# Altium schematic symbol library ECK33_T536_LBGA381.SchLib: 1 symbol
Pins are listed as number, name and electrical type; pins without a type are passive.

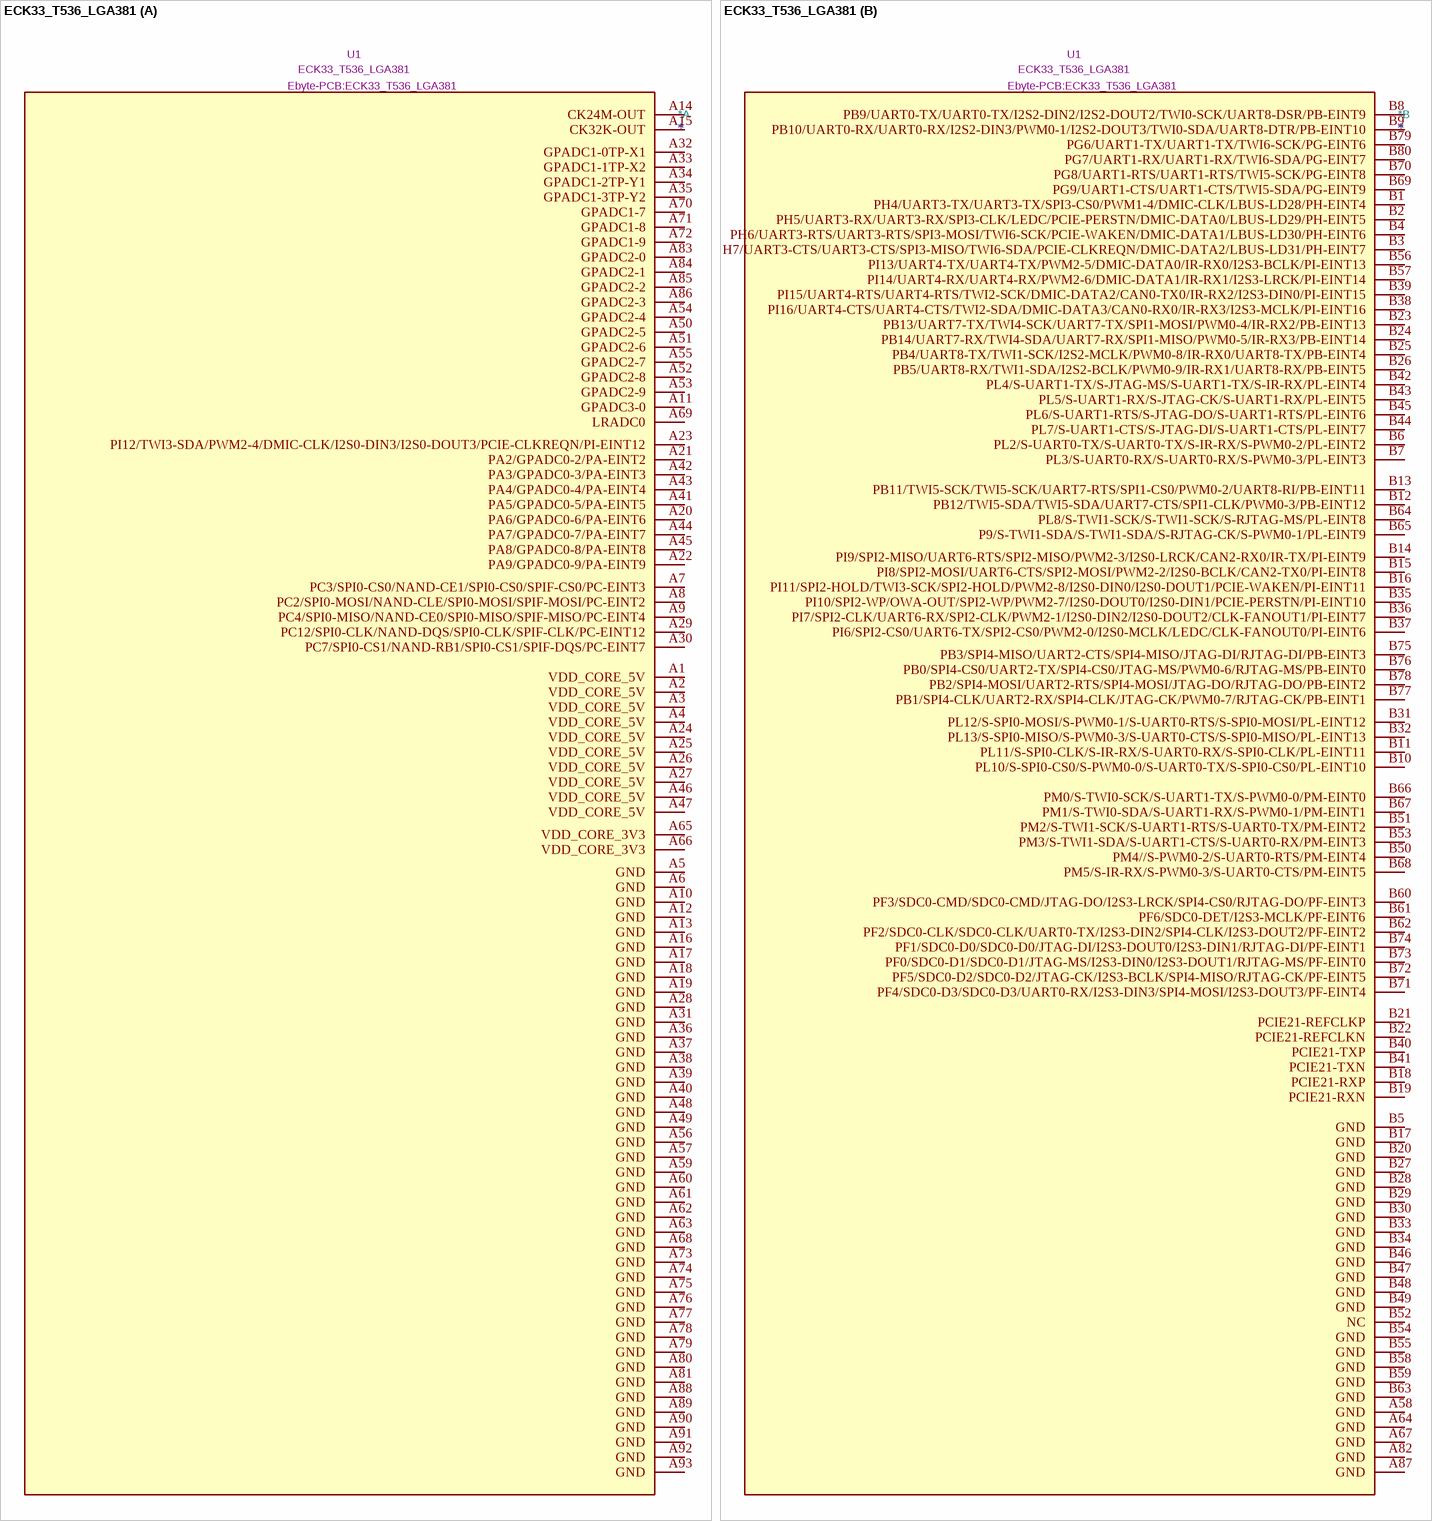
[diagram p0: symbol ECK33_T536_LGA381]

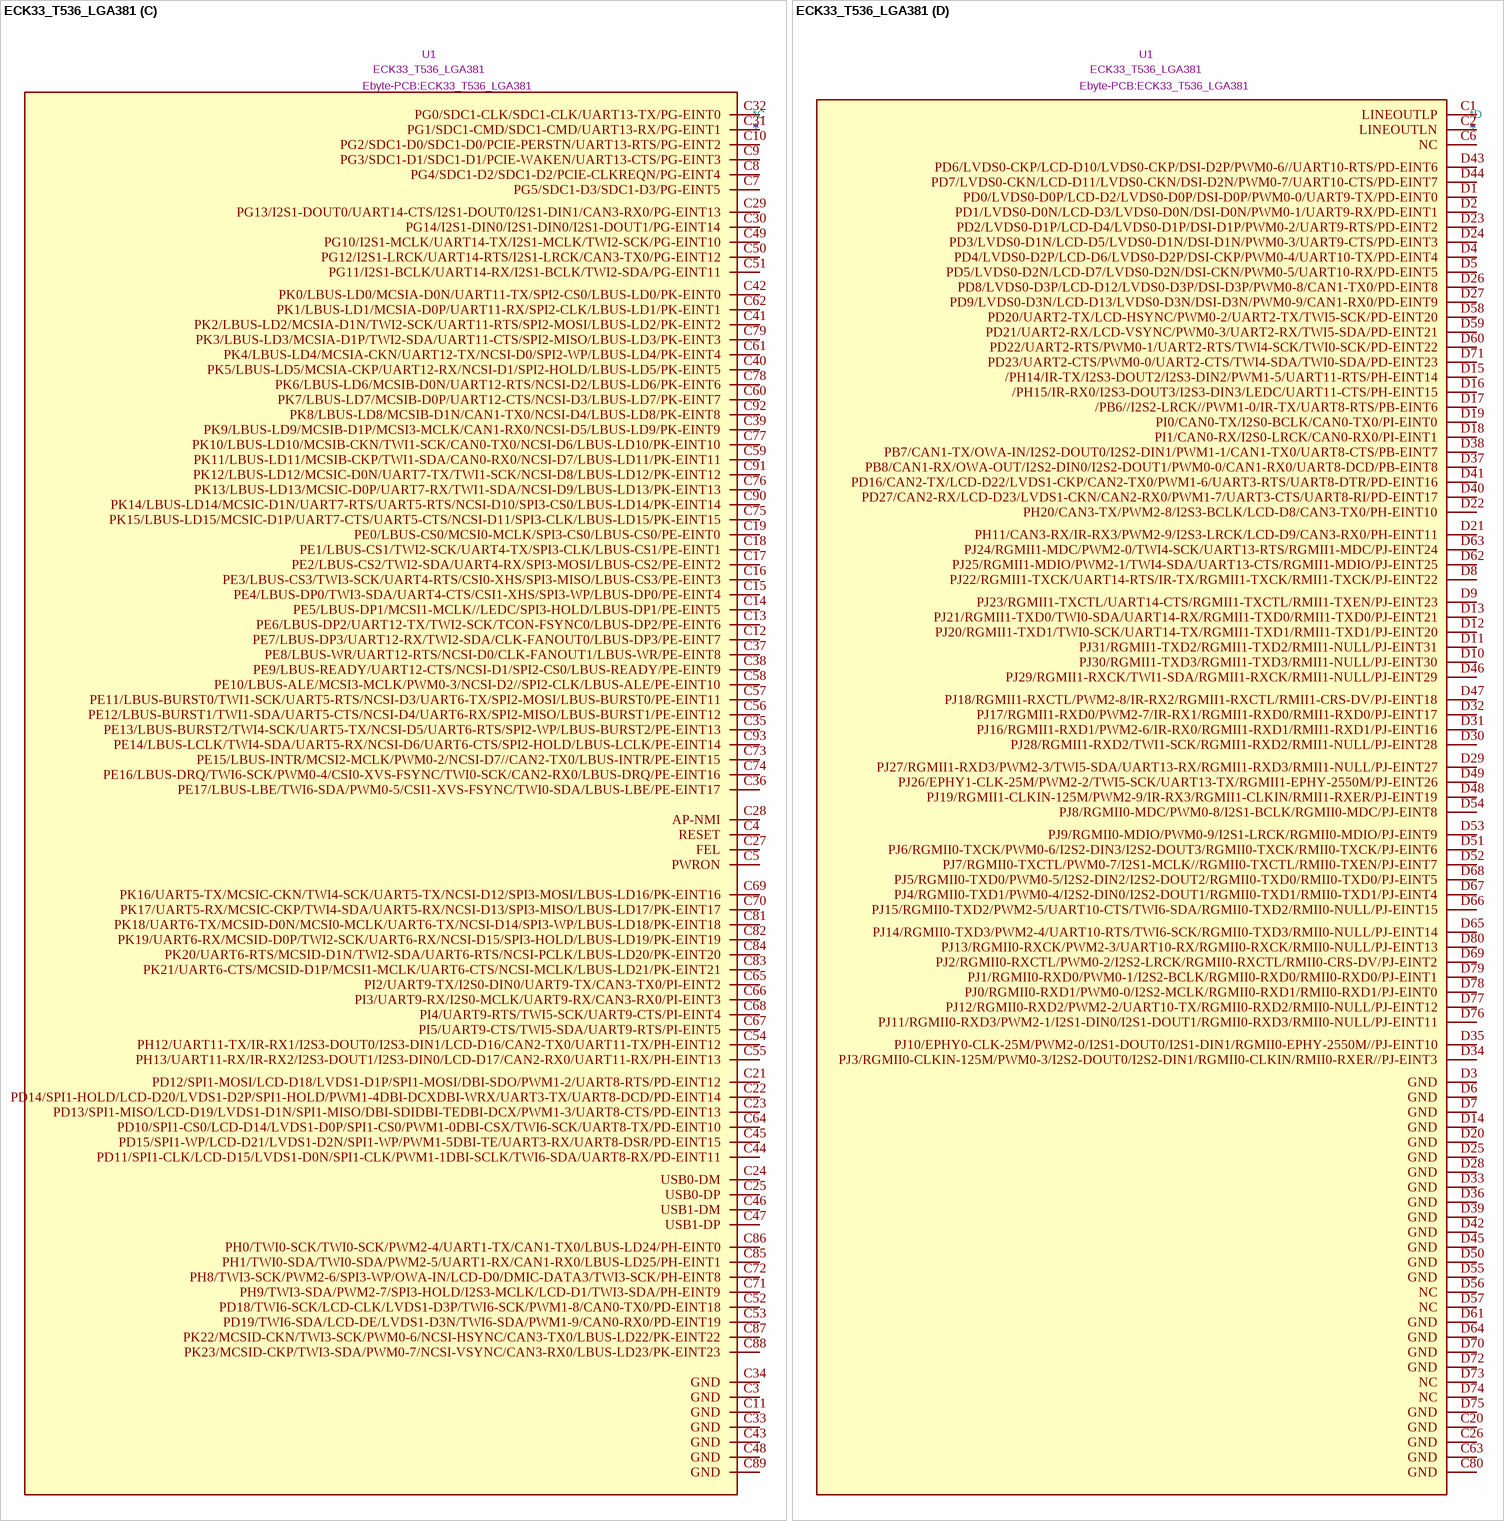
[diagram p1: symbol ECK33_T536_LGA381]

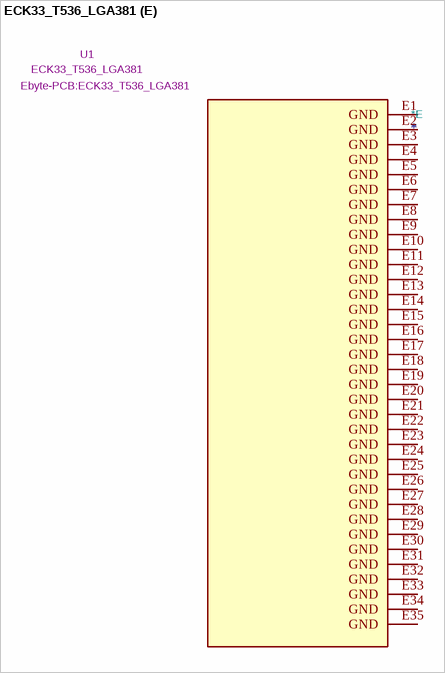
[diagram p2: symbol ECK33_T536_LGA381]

## ECK33_T536_LGA381
designator *  value ECK33_T536_LGA381  Footprint: Ebyte-PCB:ECK33_T536_LGA381  Reference: U1
part A pins: A1 VDD_CORE_5V, A2 VDD_CORE_5V, A3 VDD_CORE_5V, A4 VDD_CORE_5V, A5 GND, A6 GND, A7 PC3/SPI0-CS0/NAND-CE1/SPI0-CS0/SPIF-CS0/PC-EINT3, A8 PC2/SPI0-MOSI/NAND-CLE/SPI0-MOSI/SPIF-MOSI/PC-EINT2, A9 PC4/SPI0-MISO/NAND-CE0/SPI0-MISO/SPIF-MISO/PC-EINT4, A10 GND, A11 GPADC3-0, A12 GND, A13 GND, A14 CK24M-OUT, A15 CK32K-OUT, A16 GND, A17 GND, A18 GND, A19 GND, A20 PA6/GPADC0-6/PA-EINT6, A21 PA2/GPADC0-2/PA-EINT2, A22 PA9/GPADC0-9/PA-EINT9, A23 PI12/TWI3-SDA/PWM2-4/DMIC-CLK/I2S0-DIN3/I2S0-DOUT3/PCIE-CLKREQN/PI-EINT12, A24 VDD_CORE_5V, A25 VDD_CORE_5V, A26 VDD_CORE_5V, A27 VDD_CORE_5V, A28 GND, A29 PC12/SPI0-CLK/NAND-DQS/SPI0-CLK/SPIF-CLK/PC-EINT12, A30 PC7/SPI0-CS1/NAND-RB1/SPI0-CS1/SPIF-DQS/PC-EINT7, A31 GND, A32 GPADC1-0TP-X1, A33 GPADC1-1TP-X2, A34 GPADC1-2TP-Y1, A35 GPADC1-3TP-Y2, A36 GND, A37 GND, A38 GND, A39 GND, A40 GND, A41 PA5/GPADC0-5/PA-EINT5, A42 PA3/GPADC0-3/PA-EINT3, A43 PA4/GPADC0-4/PA-EINT4, A44 PA7/GPADC0-7/PA-EINT7, A45 PA8/GPADC0-8/PA-EINT8, A46 VDD_CORE_5V, A47 VDD_CORE_5V, A48 GND, A49 GND, A50 GPADC2-5, A51 GPADC2-6, A52 GPADC2-8, A53 GPADC2-9, A54 GPADC2-4, A55 GPADC2-7, A56 GND, A57 GND, A59 GND, A60 GND, A61 GND, A62 GND, A63 GND, A65 VDD_CORE_3V3, A66 VDD_CORE_3V3, A68 GND, A69 LRADC0, A70 GPADC1-7, A71 GPADC1-8, A72 GPADC1-9, A73 GND, A74 GND, A75 GND, A76 GND, A77 GND, A78 GND, A79 GND, A80 GND, A81 GND, A83 GPADC2-0, A84 GPADC2-1, A85 GPADC2-2, A86 GPADC2-3, A88 GND, A89 GND, A90 GND, A91 GND, A92 GND, A93 GND
part B pins: A58 GND, A64 GND, A67 GND, A82 GND, A87 GND, B1 PH4/UART3-TX/UART3-TX/SPI3-CS0/PWM1-4/DMIC-CLK/LBUS-LD28/PH-EINT4, B2 PH5/UART3-RX/UART3-RX/SPI3-CLK/LEDC/PCIE-PERSTN/DMIC-DATA0/LBUS-LD29/PH-EINT5, B3 PH7/UART3-CTS/UART3-CTS/SPI3-MISO/TWI6-SDA/PCIE-CLKREQN/DMIC-DATA2/LBUS-LD31/PH-EINT7, B4 PH6/UART3-RTS/UART3-RTS/SPI3-MOSI/TWI6-SCK/PCIE-WAKEN/DMIC-DATA1/LBUS-LD30/PH-EINT6, B5 GND, B6 PL2/S-UART0-TX/S-UART0-TX/S-IR-RX/S-PWM0-2/PL-EINT2, B7 PL3/S-UART0-RX/S-UART0-RX/S-PWM0-3/PL-EINT3, B8 PB9/UART0-TX/UART0-TX/I2S2-DIN2/I2S2-DOUT2/TWI0-SCK/UART8-DSR/PB-EINT9, B9 PB10/UART0-RX/UART0-RX/I2S2-DIN3/PWM0-1/I2S2-DOUT3/TWI0-SDA/UART8-DTR/PB-EINT10, B10 PL10/S-SPI0-CS0/S-PWM0-0/S-UART0-TX/S-SPI0-CS0/PL-EINT10, B11 PL11/S-SPI0-CLK/S-IR-RX/S-UART0-RX/S-SPI0-CLK/PL-EINT11, B12 PB12/TWI5-SDA/TWI5-SDA/UART7-CTS/SPI1-CLK/PWM0-3/PB-EINT12, B13 PB11/TWI5-SCK/TWI5-SCK/UART7-RTS/SPI1-CS0/PWM0-2/UART8-RI/PB-EINT11, B14 PI9/SPI2-MISO/UART6-RTS/SPI2-MISO/PWM2-3/I2S0-LRCK/CAN2-RX0/IR-TX/PI-EINT9, B15 PI8/SPI2-MOSI/UART6-CTS/SPI2-MOSI/PWM2-2/I2S0-BCLK/CAN2-TX0/PI-EINT8, B16 PI11/SPI2-HOLD/TWI3-SCK/SPI2-HOLD/PWM2-8/I2S0-DIN0/I2S0-DOUT1/PCIE-WAKEN/PI-EINT11, B17 GND, B18 PCIE21-RXP, B19 PCIE21-RXN, B20 GND, B21 PCIE21-REFCLKP, B22 PCIE21-REFCLKN, B23 PB13/UART7-TX/TWI4-SCK/UART7-TX/SPI1-MOSI/PWM0-4/IR-RX2/PB-EINT13, B24 PB14/UART7-RX/TWI4-SDA/UART7-RX/SPI1-MISO/PWM0-5/IR-RX3/PB-EINT14, B25 PB4/UART8-TX/TWI1-SCK/I2S2-MCLK/PWM0-8/IR-RX0/UART8-TX/PB-EINT4, B26 PB5/UART8-RX/TWI1-SDA/I2S2-BCLK/PWM0-9/IR-RX1/UART8-RX/PB-EINT5, B27 GND, B28 GND, B29 GND, B30 GND, B31 PL12/S-SPI0-MOSI/S-PWM0-1/S-UART0-RTS/S-SPI0-MOSI/PL-EINT12, B32 PL13/S-SPI0-MISO/S-PWM0-3/S-UART0-CTS/S-SPI0-MISO/PL-EINT13, B33 GND, B34 GND, B35 PI10/SPI2-WP/OWA-OUT/SPI2-WP/PWM2-7/I2S0-DOUT0/I2S0-DIN1/PCIE-PERSTN/PI-EINT10, B36 PI7/SPI2-CLK/UART6-RX/SPI2-CLK/PWM2-1/I2S0-DIN2/I2S0-DOUT2/CLK-FANOUT1/PI-EINT7, B37 PI6/SPI2-CS0/UART6-TX/SPI2-CS0/PWM2-0/I2S0-MCLK/LEDC/CLK-FANOUT0/PI-EINT6, B38 PI16/UART4-CTS/UART4-CTS/TWI2-SDA/DMIC-DATA3/CAN0-RX0/IR-RX3/I2S3-MCLK/PI-EINT16, B39 PI15/UART4-RTS/UART4-RTS/TWI2-SCK/DMIC-DATA2/CAN0-TX0/IR-RX2/I2S3-DIN0/PI-EINT15, B40 PCIE21-TXP, B41 PCIE21-TXN, B42 PL4/S-UART1-TX/S-JTAG-MS/S-UART1-TX/S-IR-RX/PL-EINT4, B43 PL5/S-UART1-RX/S-JTAG-CK/S-UART1-RX/PL-EINT5, B44 PL7/S-UART1-CTS/S-JTAG-DI/S-UART1-CTS/PL-EINT7, B45 PL6/S-UART1-RTS/S-JTAG-DO/S-UART1-RTS/PL-EINT6, B46 GND, B47 GND, B48 GND, B49 GND, B50 PM4//S-PWM0-2/S-UART0-RTS/PM-EINT4, B51 PM2/S-TWI1-SCK/S-UART1-RTS/S-UART0-TX/PM-EINT2, B52 NC, B53 PM3/S-TWI1-SDA/S-UART1-CTS/S-UART0-RX/PM-EINT3, B54 GND, B55 GND, B56 PI13/UART4-TX/UART4-TX/PWM2-5/DMIC-DATA0/IR-RX0/I2S3-BCLK/PI-EINT13, B57 PI14/UART4-RX/UART4-RX/PWM2-6/DMIC-DATA1/IR-RX1/I2S3-LRCK/PI-EINT14, B58 GND, B59 GND, B60 PF3/SDC0-CMD/SDC0-CMD/JTAG-DO/I2S3-LRCK/SPI4-CS0/RJTAG-DO/PF-EINT3, B61 PF6/SDC0-DET/I2S3-MCLK/PF-EINT6, B62 PF2/SDC0-CLK/SDC0-CLK/UART0-TX/I2S3-DIN2/SPI4-CLK/I2S3-DOUT2/PF-EINT2, B63 GND, B64 PL8/S-TWI1-SCK/S-TWI1-SCK/S-RJTAG-MS/PL-EINT8, B65 P9/S-TWI1-SDA/S-TWI1-SDA/S-RJTAG-CK/S-PWM0-1/PL-EINT9, B66 PM0/S-TWI0-SCK/S-UART1-TX/S-PWM0-0/PM-EINT0, B67 PM1/S-TWI0-SDA/S-UART1-RX/S-PWM0-1/PM-EINT1, B68 PM5/S-IR-RX/S-PWM0-3/S-UART0-CTS/PM-EINT5, B69 PG9/UART1-CTS/UART1-CTS/TWI5-SDA/PG-EINT9, B70 PG8/UART1-RTS/UART1-RTS/TWI5-SCK/PG-EINT8, B71 PF4/SDC0-D3/SDC0-D3/UART0-RX/I2S3-DIN3/SPI4-MOSI/I2S3-DOUT3/PF-EINT4, B72 PF5/SDC0-D2/SDC0-D2/JTAG-CK/I2S3-BCLK/SPI4-MISO/RJTAG-CK/PF-EINT5, B73 PF0/SDC0-D1/SDC0-D1/JTAG-MS/I2S3-DIN0/I2S3-DOUT1/RJTAG-MS/PF-EINT0, B74 PF1/SDC0-D0/SDC0-D0/JTAG-DI/I2S3-DOUT0/I2S3-DIN1/RJTAG-DI/PF-EINT1, B75 PB3/SPI4-MISO/UART2-CTS/SPI4-MISO/JTAG-DI/RJTAG-DI/PB-EINT3, B76 PB0/SPI4-CS0/UART2-TX/SPI4-CS0/JTAG-MS/PWM0-6/RJTAG-MS/PB-EINT0, B77 PB1/SPI4-CLK/UART2-RX/SPI4-CLK/JTAG-CK/PWM0-7/RJTAG-CK/PB-EINT1, B78 PB2/SPI4-MOSI/UART2-RTS/SPI4-MOSI/JTAG-DO/RJTAG-DO/PB-EINT2, B79 PG6/UART1-TX/UART1-TX/TWI6-SCK/PG-EINT6, B80 PG7/UART1-RX/UART1-RX/TWI6-SDA/PG-EINT7
part C pins: C3 GND, C4 RESET, C5 PWRON, C7 PG5/SDC1-D3/SDC1-D3/PG-EINT5, C8 PG4/SDC1-D2/SDC1-D2/PCIE-CLKREQN/PG-EINT4, C9 PG3/SDC1-D1/SDC1-D1/PCIE-WAKEN/UART13-CTS/PG-EINT3, C10 PG2/SDC1-D0/SDC1-D0/PCIE-PERSTN/UART13-RTS/PG-EINT2, C11 GND, C12 PE7/LBUS-DP3/UART12-RX/TWI2-SDA/CLK-FANOUT0/LBUS-DP3/PE-EINT7, C13 PE6/LBUS-DP2/UART12-TX/TWI2-SCK/TCON-FSYNC0/LBUS-DP2/PE-EINT6, C14 PE5/LBUS-DP1/MCSI1-MCLK//LEDC/SPI3-HOLD/LBUS-DP1/PE-EINT5, C15 PE4/LBUS-DP0/TWI3-SDA/UART4-CTS/CSI1-XHS/SPI3-WP/LBUS-DP0/PE-EINT4, C16 PE3/LBUS-CS3/TWI3-SCK/UART4-RTS/CSI0-XHS/SPI3-MISO/LBUS-CS3/PE-EINT3, C17 PE2/LBUS-CS2/TWI2-SDA/UART4-RX/SPI3-MOSI/LBUS-CS2/PE-EINT2, C18 PE1/LBUS-CS1/TWI2-SCK/UART4-TX/SPI3-CLK/LBUS-CS1/PE-EINT1, C19 PE0/LBUS-CS0/MCSI0-MCLK/SPI3-CS0/LBUS-CS0/PE-EINT0, C21 PD12/SPI1-MOSI/LCD-D18/LVDS1-D1P/SPI1-MOSI/DBI-SDO/PWM1-2/UART8-RTS/PD-EINT12, C22 PD14/SPI1-HOLD/LCD-D20/LVDS1-D2P/SPI1-HOLD/PWM1-4DBI-DCXDBI-WRX/UART3-TX/UART8-DCD/PD-EINT14, C23 PD13/SPI1-MISO/LCD-D19/LVDS1-D1N/SPI1-MISO/DBI-SDIDBI-TEDBI-DCX/PWM1-3/UART8-CTS/PD-EINT13, C24 USB0-DM, C25 USB0-DP, C27 FEL, C28 AP-NMI, C29 PG13/I2S1-DOUT0/UART14-CTS/I2S1-DOUT0/I2S1-DIN1/CAN3-RX0/PG-EINT13, C30 PG14/I2S1-DIN0/I2S1-DIN0/I2S1-DOUT1/PG-EINT14, C31 PG1/SDC1-CMD/SDC1-CMD/UART13-RX/PG-EINT1, C32 PG0/SDC1-CLK/SDC1-CLK/UART13-TX/PG-EINT0, C33 GND, C34 GND, C35 PE13/LBUS-BURST2/TWI4-SCK/UART5-TX/NCSI-D5/UART6-RTS/SPI2-WP/LBUS-BURST2/PE-EINT13, C36 PE17/LBUS-LBE/TWI6-SDA/PWM0-5/CSI1-XVS-FSYNC/TWI0-SDA/LBUS-LBE/PE-EINT17, C37 PE8/LBUS-WR/UART12-RTS/NCSI-D0/CLK-FANOUT1/LBUS-WR/PE-EINT8, C38 PE9/LBUS-READY/UART12-CTS/NCSI-D1/SPI2-CS0/LBUS-READY/PE-EINT9, C39 PK9/LBUS-LD9/MCSIB-D1P/MCSI3-MCLK/CAN1-RX0/NCSI-D5/LBUS-LD9/PK-EINT9, C40 PK5/LBUS-LD5/MCSIA-CKP/UART12-RX/NCSI-D1/SPI2-HOLD/LBUS-LD5/PK-EINT5, C41 PK2/LBUS-LD2/MCSIA-D1N/TWI2-SCK/UART11-RTS/SPI2-MOSI/LBUS-LD2/PK-EINT2, C42 PK0/LBUS-LD0/MCSIA-D0N/UART11-TX/SPI2-CS0/LBUS-LD0/PK-EINT0, C43 GND, C44 PD11/SPI1-CLK/LCD-D15/LVDS1-D0N/SPI1-CLK/PWM1-1DBI-SCLK/TWI6-SDA/UART8-RX/PD-EINT11, C45 PD15/SPI1-WP/LCD-D21/LVDS1-D2N/SPI1-WP/PWM1-5DBI-TE/UART3-RX/UART8-DSR/PD-EINT15, C46 USB1-DM, C47 USB1-DP, C48 GND, C49 PG10/I2S1-MCLK/UART14-TX/I2S1-MCLK/TWI2-SCK/PG-EINT10, C50 PG12/I2S1-LRCK/UART14-RTS/I2S1-LRCK/CAN3-TX0/PG-EINT12, C51 PG11/I2S1-BCLK/UART14-RX/I2S1-BCLK/TWI2-SDA/PG-EINT11, C52 PD18/TWI6-SCK/LCD-CLK/LVDS1-D3P/TWI6-SCK/PWM1-8/CAN0-TX0/PD-EINT18, C53 PD19/TWI6-SDA/LCD-DE/LVDS1-D3N/TWI6-SDA/PWM1-9/CAN0-RX0/PD-EINT19, C54 PH12/UART11-TX/IR-RX1/I2S3-DOUT0/I2S3-DIN1/LCD-D16/CAN2-TX0/UART11-TX/PH-EINT12, C55 PH13/UART11-RX/IR-RX2/I2S3-DOUT1/I2S3-DIN0/LCD-D17/CAN2-RX0/UART11-RX/PH-EINT13, C56 PE12/LBUS-BURST1/TWI1-SDA/UART5-CTS/NCSI-D4/UART6-RX/SPI2-MISO/LBUS-BURST1/PE-EINT12, C57 PE11/LBUS-BURST0/TWI1-SCK/UART5-RTS/NCSI-D3/UART6-TX/SPI2-MOSI/LBUS-BURST0/PE-EINT11, C58 PE10/LBUS-ALE/MCSI3-MCLK/PWM0-3/NCSI-D2//SPI2-CLK/LBUS-ALE/PE-EINT10, C59 PK11/LBUS-LD11/MCSIB-CKP/TWI1-SDA/CAN0-RX0/NCSI-D7/LBUS-LD11/PK-EINT11, C60 PK7/LBUS-LD7/MCSIB-D0P/UART12-CTS/NCSI-D3/LBUS-LD7/PK-EINT7, C61 PK4/LBUS-LD4/MCSIA-CKN/UART12-TX/NCSI-D0/SPI2-WP/LBUS-LD4/PK-EINT4, C62 PK1/LBUS-LD1/MCSIA-D0P/UART11-RX/SPI2-CLK/LBUS-LD1/PK-EINT1, C64 PD10/SPI1-CS0/LCD-D14/LVDS1-D0P/SPI1-CS0/PWM1-0DBI-CSX/TWI6-SCK/UART8-TX/PD-EINT10, C65 PI2/UART9-TX/I2S0-DIN0/UART9-TX/CAN3-TX0/PI-EINT2, C66 PI3/UART9-RX/I2S0-MCLK/UART9-RX/CAN3-RX0/PI-EINT3, C67 PI5/UART9-CTS/TWI5-SDA/UART9-RTS/PI-EINT5, C68 PI4/UART9-RTS/TWI5-SCK/UART9-CTS/PI-EINT4, C69 PK16/UART5-TX/MCSIC-CKN/TWI4-SCK/UART5-TX/NCSI-D12/SPI3-MOSI/LBUS-LD16/PK-EINT16, C70 PK17/UART5-RX/MCSIC-CKP/TWI4-SDA/UART5-RX/NCSI-D13/SPI3-MISO/LBUS-LD17/PK-EINT17, C71 PH9/TWI3-SDA/PWM2-7/SPI3-HOLD/I2S3-MCLK/LCD-D1/TWI3-SDA/PH-EINT9, C72 PH8/TWI3-SCK/PWM2-6/SPI3-WP/OWA-IN/LCD-D0/DMIC-DATA3/TWI3-SCK/PH-EINT8, C73 PE15/LBUS-INTR/MCSI2-MCLK/PWM0-2/NCSI-D7//CAN2-TX0/LBUS-INTR/PE-EINT15, C74 PE16/LBUS-DRQ/TWI6-SCK/PWM0-4/CSI0-XVS-FSYNC/TWI0-SCK/CAN2-RX0/LBUS-DRQ/PE-EINT16, C75 PK15/LBUS-LD15/MCSIC-D1P/UART7-CTS/UART5-CTS/NCSI-D11/SPI3-CLK/LBUS-LD15/PK-EINT15, C76 PK13/LBUS-LD13/MCSIC-D0P/UART7-RX/TWI1-SDA/NCSI-D9/LBUS-LD13/PK-EINT13, C77 PK10/LBUS-LD10/MCSIB-CKN/TWI1-SCK/CAN0-TX0/NCSI-D6/LBUS-LD10/PK-EINT10, C78 PK6/LBUS-LD6/MCSIB-D0N/UART12-RTS/NCSI-D2/LBUS-LD6/PK-EINT6, C79 PK3/LBUS-LD3/MCSIA-D1P/TWI2-SDA/UART11-CTS/SPI2-MISO/LBUS-LD3/PK-EINT3, C81 PK18/UART6-TX/MCSID-D0N/MCSI0-MCLK/UART6-TX/NCSI-D14/SPI3-WP/LBUS-LD18/PK-EINT18, C82 PK19/UART6-RX/MCSID-D0P/TWI2-SCK/UART6-RX/NCSI-D15/SPI3-HOLD/LBUS-LD19/PK-EINT19, C83 PK21/UART6-CTS/MCSID-D1P/MCSI1-MCLK/UART6-CTS/NCSI-MCLK/LBUS-LD21/PK-EINT21, C84 PK20/UART6-RTS/MCSID-D1N/TWI2-SDA/UART6-RTS/NCSI-PCLK/LBUS-LD20/PK-EINT20, C85 PH1/TWI0-SDA/TWI0-SDA/PWM2-5/UART1-RX/CAN1-RX0/LBUS-LD25/PH-EINT1, C86 PH0/TWI0-SCK/TWI0-SCK/PWM2-4/UART1-TX/CAN1-TX0/LBUS-LD24/PH-EINT0, C87 PK22/MCSID-CKN/TWI3-SCK/PWM0-6/NCSI-HSYNC/CAN3-TX0/LBUS-LD22/PK-EINT22, C88 PK23/MCSID-CKP/TWI3-SDA/PWM0-7/NCSI-VSYNC/CAN3-RX0/LBUS-LD23/PK-EINT23, C89 GND, C90 PK14/LBUS-LD14/MCSIC-D1N/UART7-RTS/UART5-RTS/NCSI-D10/SPI3-CS0/LBUS-LD14/PK-EINT14, C91 PK12/LBUS-LD12/MCSIC-D0N/UART7-TX/TWI1-SCK/NCSI-D8/LBUS-LD12/PK-EINT12, C92 PK8/LBUS-LD8/MCSIB-D1N/CAN1-TX0/NCSI-D4/LBUS-LD8/PK-EINT8, C93 PE14/LBUS-LCLK/TWI4-SDA/UART5-RX/NCSI-D6/UART6-CTS/SPI2-HOLD/LBUS-LCLK/PE-EINT14
part D pins: C1 LINEOUTLP, C2 LINEOUTLN, C6 NC, C20 GND, C26 GND, C63 GND, C80 GND, D1 PD0/LVDS0-D0P/LCD-D2/LVDS0-D0P/DSI-D0P/PWM0-0/UART9-TX/PD-EINT0, D2 PD1/LVDS0-D0N/LCD-D3/LVDS0-D0N/DSI-D0N/PWM0-1/UART9-RX/PD-EINT1, D3 GND, D4 PD4/LVDS0-D2P/LCD-D6/LVDS0-D2P/DSI-CKP/PWM0-4/UART10-TX/PD-EINT4, D5 PD5/LVDS0-D2N/LCD-D7/LVDS0-D2N/DSI-CKN/PWM0-5/UART10-RX/PD-EINT5, D6 GND, D7 GND, D8 PJ22/RGMII1-TXCK/UART14-RTS/IR-TX/RGMII1-TXCK/RMII1-TXCK/PJ-EINT22, D9 PJ23/RGMII1-TXCTL/UART14-CTS/RGMII1-TXCTL/RMII1-TXEN/PJ-EINT23, D10 PJ30/RGMII1-TXD3/RGMII1-TXD3/RMII1-NULL/PJ-EINT30, D11 PJ31/RGMII1-TXD2/RGMII1-TXD2/RMII1-NULL/PJ-EINT31, D12 PJ20/RGMII1-TXD1/TWI0-SCK/UART14-TX/RGMII1-TXD1/RMII1-TXD1/PJ-EINT20, D13 PJ21/RGMII1-TXD0/TWI0-SDA/UART14-RX/RGMII1-TXD0/RMII1-TXD0/PJ-EINT21, D14 GND, D15 /PH14/IR-TX/I2S3-DOUT2/I2S3-DIN2/PWM1-5/UART11-RTS/PH-EINT14, D16 /PH15/IR-RX0/I2S3-DOUT3/I2S3-DIN3/LEDC/UART11-CTS/PH-EINT15, D17 /PB6//I2S2-LRCK//PWM1-0/IR-TX/UART8-RTS/PB-EINT6, D18 PI1/CAN0-RX/I2S0-LRCK/CAN0-RX0/PI-EINT1, D19 PI0/CAN0-TX/I2S0-BCLK/CAN0-TX0/PI-EINT0, D20 GND, D21 PH11/CAN3-RX/IR-RX3/PWM2-9/I2S3-LRCK/LCD-D9/CAN3-RX0/PH-EINT11, D22 PH20/CAN3-TX/PWM2-8/I2S3-BCLK/LCD-D8/CAN3-TX0/PH-EINT10, D23 PD2/LVDS0-D1P/LCD-D4/LVDS0-D1P/DSI-D1P/PWM0-2/UART9-RTS/PD-EINT2, D24 PD3/LVDS0-D1N/LCD-D5/LVDS0-D1N/DSI-D1N/PWM0-3/UART9-CTS/PD-EINT3, D25 GND, D26 PD8/LVDS0-D3P/LCD-D12/LVDS0-D3P/DSI-D3P/PWM0-8/CAN1-TX0/PD-EINT8, D27 PD9/LVDS0-D3N/LCD-D13/LVDS0-D3N/DSI-D3N/PWM0-9/CAN1-RX0/PD-EINT9, D28 GND, D29 PJ27/RGMII1-RXD3/PWM2-3/TWI5-SDA/UART13-RX/RGMII1-RXD3/RMII1-NULL/PJ-EINT27, D30 PJ28/RGMII1-RXD2/TWI1-SCK/RGMII1-RXD2/RMII1-NULL/PJ-EINT28, D31 PJ16/RGMII1-RXD1/PWM2-6/IR-RX0/RGMII1-RXD1/RMII1-RXD1/PJ-EINT16, D32 PJ17/RGMII1-RXD0/PWM2-7/IR-RX1/RGMII1-RXD0/RMII1-RXD0/PJ-EINT17, D33 GND, D34 PJ3/RGMII0-CLKIN-125M/PWM0-3/I2S2-DOUT0/I2S2-DIN1/RGMII0-CLKIN/RMII0-RXER//PJ-EINT3, D35 PJ10/EPHY0-CLK-25M/PWM2-0/I2S1-DOUT0/I2S1-DIN1/RGMII0-EPHY-2550M//PJ-EINT10, D36 GND, D37 PB8/CAN1-RX/OWA-OUT/I2S2-DIN0/I2S2-DOUT1/PWM0-0/CAN1-RX0/UART8-DCD/PB-EINT8, D38 PB7/CAN1-TX/OWA-IN/I2S2-DOUT0/I2S2-DIN1/PWM1-1/CAN1-TX0/UART8-CTS/PB-EINT7, D39 GND, D40 PD27/CAN2-RX/LCD-D23/LVDS1-CKN/CAN2-RX0/PWM1-7/UART3-CTS/UART8-RI/PD-EINT17, D41 PD16/CAN2-TX/LCD-D22/LVDS1-CKP/CAN2-TX0/PWM1-6/UART3-RTS/UART8-DTR/PD-EINT16, D42 GND, D43 PD6/LVDS0-CKP/LCD-D10/LVDS0-CKP/DSI-D2P/PWM0-6//UART10-RTS/PD-EINT6, D44 PD7/LVDS0-CKN/LCD-D11/LVDS0-CKN/DSI-D2N/PWM0-7/UART10-CTS/PD-EINT7, D45 GND, D46 PJ29/RGMII1-RXCK/TWI1-SDA/RGMII1-RXCK/RMII1-NULL/PJ-EINT29, D47 PJ18/RGMII1-RXCTL/PWM2-8/IR-RX2/RGMII1-RXCTL/RMII1-CRS-DV/PJ-EINT18, D48 PJ19/RGMII1-CLKIN-125M/PWM2-9/IR-RX3/RGMII1-CLKIN/RMII1-RXER/PJ-EINT19, D49 PJ26/EPHY1-CLK-25M/PWM2-2/TWI5-SCK/UART13-TX/RGMII1-EPHY-2550M/PJ-EINT26, D50 GND, D51 PJ6/RGMII0-TXCK/PWM0-6/I2S2-DIN3/I2S2-DOUT3/RGMII0-TXCK/RMII0-TXCK/PJ-EINT6, D52 PJ7/RGMII0-TXCTL/PWM0-7/I2S1-MCLK//RGMII0-TXCTL/RMII0-TXEN/PJ-EINT7, D53 PJ9/RGMII0-MDIO/PWM0-9/I2S1-LRCK/RGMII0-MDIO/PJ-EINT9, D54 PJ8/RGMII0-MDC/PWM0-8/I2S1-BCLK/RGMII0-MDC/PJ-EINT8, D55 GND, D56 NC, D57 NC, D58 PD20/UART2-TX/LCD-HSYNC/PWM0-2/UART2-TX/TWI5-SCK/PD-EINT20, D59 PD21/UART2-RX/LCD-VSYNC/PWM0-3/UART2-RX/TWI5-SDA/PD-EINT21, D60 PD22/UART2-RTS/PWM0-1/UART2-RTS/TWI4-SCK/TWI0-SCK/PD-EINT22, D61 GND, D62 PJ25/RGMII1-MDIO/PWM2-1/TWI4-SDA/UART13-CTS/RGMII1-MDIO/PJ-EINT25, D63 PJ24/RGMII1-MDC/PWM2-0/TWI4-SCK/UART13-RTS/RGMII1-MDC/PJ-EINT24, D64 GND, D65 PJ14/RGMII0-TXD3/PWM2-4/UART10-RTS/TWI6-SCK/RGMII0-TXD3/RMII0-NULL/PJ-EINT14, D66 PJ15/RGMII0-TXD2/PWM2-5/UART10-CTS/TWI6-SDA/RGMII0-TXD2/RMII0-NULL/PJ-EINT15, D67 PJ4/RGMII0-TXD1/PWM0-4/I2S2-DIN0/I2S2-DOUT1/RGMII0-TXD1/RMII0-TXD1/PJ-EINT4, D68 PJ5/RGMII0-TXD0/PWM0-5/I2S2-DIN2/I2S2-DOUT2/RGMII0-TXD0/RMII0-TXD0/PJ-EINT5, D69 PJ2/RGMII0-RXCTL/PWM0-2/I2S2-LRCK/RGMII0-RXCTL/RMII0-CRS-DV/PJ-EINT2, D70 GND, D71 PD23/UART2-CTS/PWM0-0/UART2-CTS/TWI4-SDA/TWI0-SDA/PD-EINT23, D72 GND, D73 NC, D74 NC, D75 GND, D76 PJ11/RGMII0-RXD3/PWM2-1/I2S1-DIN0/I2S1-DOUT1/RGMII0-RXD3/RMII0-NULL/PJ-EINT11, D77 PJ12/RGMII0-RXD2/PWM2-2/UART10-TX/RGMII0-RXD2/RMII0-NULL/PJ-EINT12, D78 PJ0/RGMII0-RXD1/PWM0-0/I2S2-MCLK/RGMII0-RXD1/RMII0-RXD1/PJ-EINT0, D79 PJ1/RGMII0-RXD0/PWM0-1/I2S2-BCLK/RGMII0-RXD0/RMII0-RXD0/PJ-EINT1, D80 PJ13/RGMII0-RXCK/PWM2-3/UART10-RX/RGMII0-RXCK/RMII0-NULL/PJ-EINT13
part E pins: E1 GND, E2 GND, E3 GND, E4 GND, E5 GND, E6 GND, E7 GND, E8 GND, E9 GND, E10 GND, E11 GND, E12 GND, E13 GND, E14 GND, E15 GND, E16 GND, E17 GND, E18 GND, E19 GND, E20 GND, E21 GND, E22 GND, E23 GND, E24 GND, E25 GND, E26 GND, E27 GND, E28 GND, E29 GND, E30 GND, E31 GND, E32 GND, E33 GND, E34 GND, E35 GND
